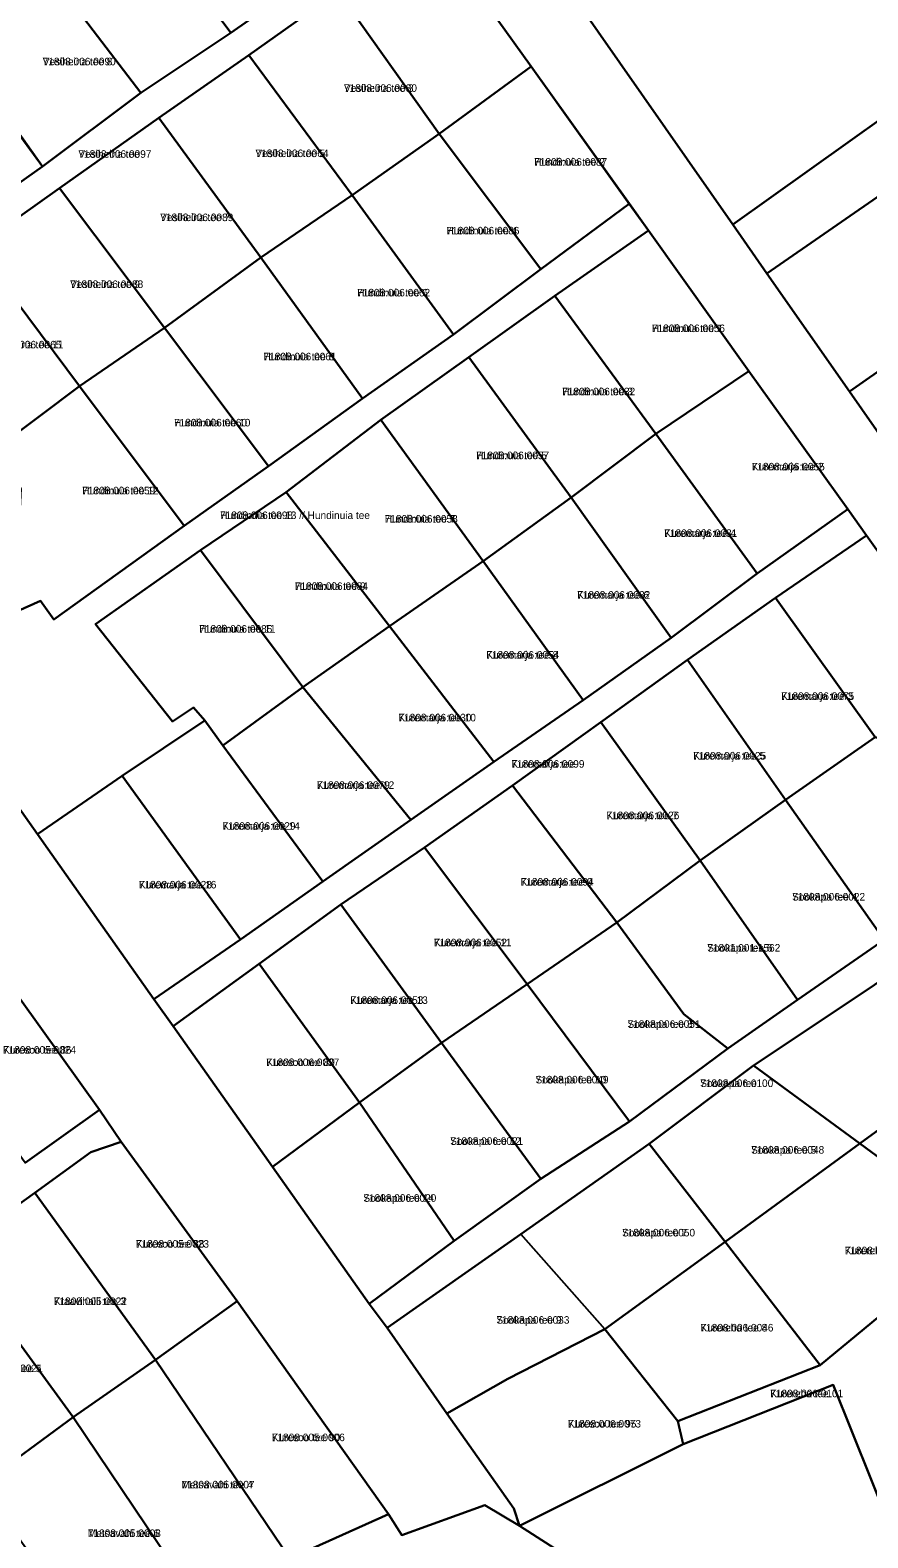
# Model space of a CAD drawing. Extents: x 529768 to 552006, y 6562269 to 6580975.
# Drawn here: x 537073.5 to 537239.9, y 6569374.1 to 6569673.6 of the extents above; entities that cross this region are included whole.
import ezdxf

# ---------------------------------------------------------------- set-up
doc = ezdxf.new("R2010")
doc.units = 0
for name, color, linetype in [('L_AADRESS', 7, 'Continuous'), ('PIIR', 7, 'Continuous'), ('TUNNUS', 7, 'Continuous')]:
    doc.layers.add(name, color=color, linetype=linetype)

msp = doc.modelspace()

# ---------------------------------------------------------------- linework, layer by layer
at = {"layer": 'PIIR'}
for points in [[(537266.4, 6569673.05), (537213.13, 6569635.04), (537177.27, 6569686.31), (537203.34, 6569704.49), (537225.59, 6569720.1), (537248.43, 6569736.1)], [(537261.05, 6569543.39), (537239.66, 6569573.28), (537235.95, 6569578.47), (537216.31, 6569605.91), (537196.34, 6569633.83), (537192.57, 6569639.15), (537173.03, 6569666.4), (537152.81, 6569694.66)], [(537177.27, 6569686.31), (537213.13, 6569635.04), (537219.84, 6569625.32), (537236.26, 6569601.86), (537251.93, 6569579.48)], [(537245.2, 6569642.81), (537219.84, 6569625.32), (537213.13, 6569635.04), (537266.4, 6569673.05)], [(537071.01, 6569558.23), (537075.59, 6569560.29), (537078.22, 6569556.56), (537104.13, 6569575.18), (537120.88, 6569587.03), (537139.57, 6569600.46), (537157.6, 6569613.15), (537174.96, 6569626.16), (537192.55, 6569639.13), (537196.34, 6569633.83), (537177.78, 6569620.87), (537160.65, 6569608.69), (537143.21, 6569596.23), (537124.4, 6569581.87), (537107.37, 6569570.33), (537086.55, 6569555.63), (537101.84, 6569536.3), (537105.98, 6569539.09), (537108.23, 6569536.47), (537091.83, 6569525.51), (537074.98, 6569513.91), (537038.34, 6569565.76)], [(536660.44, 6569597.72), (536680.38, 6569359.64), (536681.71, 6569343.63), (536686.07, 6569338.44), (536784.68, 6569221.92), (536962.4, 6569293.88), (536967.09, 6569295.8), (536965.47, 6569313.36), (536978.54, 6569310.73), (536993.55, 6569314.63), (536997.71, 6569316.46), (537012.75, 6569322.66), (537032.22, 6569330.68), (537054.2, 6569339.74), (537061.66, 6569342.81), (537086.06, 6569353.34), (537106.33, 6569362.09), (537125.11, 6569370.01), (537144.7, 6569378.86), (537147.4, 6569374.65), (537163.87, 6569380.63), (537170.73, 6569376.5), (537249.6, 6569325.97)], [(537038.34, 6569565.76), (537074.98, 6569513.91), (537098.12, 6569481.17), (537101.92, 6569475.79), (537121.67, 6569447.83), (537140.89, 6569420.64), (537144.46, 6569415.89), (537156.29, 6569398.85), (537169.61, 6569380), (537170.73, 6569376.5), (537163.87, 6569380.63), (537147.4, 6569374.65), (537144.7, 6569378.86), (537114.67, 6569421.13), (537091.6, 6569452.84), (537087.31, 6569459.19), (537063.91, 6569491.83)], [(537072.57, 6569448.65), (537087.31, 6569459.19), (537091.6, 6569452.84), (537085.62, 6569450.74), (537074.45, 6569442.68), (537058.12, 6569430.98)], [(537251.88, 6569357.54), (537233.07, 6569404.52), (537203.24, 6569392.77), (537202.16, 6569397.33), (537230.45, 6569408.44), (537262.38, 6569434.81)]]:
    msp.add_lwpolyline(points, dxfattribs=at)
for points in [[(537131.6, 6569685.88), (537113.43, 6569673.07), (537093.32, 6569700.01), (537111.74, 6569713.13)], [(537093.32, 6569700.01), (537113.43, 6569673.07), (537095.55, 6569661.17), (537075.56, 6569687.37)], [(537149.74, 6569698.95), (537152.81, 6569694.66), (537134.74, 6569681.28), (537116.99, 6569668.66), (537099.09, 6569656.2), (537079.39, 6569642.24), (537062.78, 6569630.47), (537047.13, 6569619.41), (537031.67, 6569608.68), (537015.83, 6569597.61), (537012.9, 6569601.76), (537028.62, 6569613.04), (537044.19, 6569623.89), (537059.55, 6569634.95), (537076.02, 6569646.54), (537095.55, 6569661.17), (537113.43, 6569673.07), (537131.6, 6569685.88)], [(537173.03, 6569666.4), (537154.76, 6569653.04), (537134.74, 6569681.28), (537152.81, 6569694.66)], [(537075.56, 6569687.37), (537095.55, 6569661.17), (537076.02, 6569646.54), (537056.52, 6569673.94)], [(537154.76, 6569653.04), (537137.51, 6569640.87), (537116.99, 6569668.66), (537134.74, 6569681.28)], [(537076.02, 6569646.54), (537059.55, 6569634.95), (537039.53, 6569661.72), (537056.18, 6569673.57)], [(537137.51, 6569640.87), (537119.38, 6569628.48), (537099.09, 6569656.2), (537116.99, 6569668.66)], [(537154.76, 6569653.04), (537173.03, 6569666.4), (537192.55, 6569639.13), (537174.96, 6569626.16)], [(537099.09, 6569656.2), (537119.38, 6569628.48), (537100.23, 6569614.48), (537079.39, 6569642.24)], [(537137.51, 6569640.87), (537154.76, 6569653.04), (537174.96, 6569626.16), (537157.6, 6569613.15)], [(537079.39, 6569642.24), (537100.23, 6569614.48), (537083.35, 6569602.94), (537062.78, 6569630.47)], [(537137.51, 6569640.87), (537157.6, 6569613.15), (537139.57, 6569600.46), (537119.38, 6569628.48)], [(537245.2, 6569642.81), (537261.35, 6569619.4), (537236.26, 6569601.86), (537219.84, 6569625.32)], [(537216.31, 6569605.91), (537197.79, 6569593.45), (537177.78, 6569620.87), (537196.34, 6569633.83)], [(537047.13, 6569619.41), (537062.78, 6569630.47), (537083.35, 6569602.94), (537067.23, 6569590.84)], [(537139.57, 6569600.46), (537120.88, 6569587.03), (537100.23, 6569614.48), (537119.38, 6569628.48)], [(537160.65, 6569608.69), (537177.78, 6569620.87), (537197.79, 6569593.45), (537181.03, 6569580.83)], [(537236.26, 6569601.86), (537261.35, 6569619.4), (537276.9, 6569597.32), (537251.93, 6569579.48)], [(537100.23, 6569614.48), (537120.88, 6569587.03), (537104.13, 6569575.18), (537083.35, 6569602.94)], [(537181.03, 6569580.83), (537163.54, 6569568.18), (537143.21, 6569596.23), (537160.65, 6569608.69)], [(537235.95, 6569578.47), (537217.96, 6569565.73), (537197.79, 6569593.45), (537216.31, 6569605.91)], [(537068.21, 6569572.85), (537071.43, 6569575.92), (537071.74, 6569582.52), (537067.23, 6569590.84), (537083.35, 6569602.94), (537104.13, 6569575.18), (537078.22, 6569556.56), (537075.59, 6569560.29), (537071.01, 6569558.23), (537063.64, 6569571.75)], [(537124.4, 6569581.87), (537143.21, 6569596.23), (537163.54, 6569568.18), (537144.89, 6569555.25)], [(537197.79, 6569593.45), (537217.96, 6569565.73), (537200.85, 6569552.93), (537181.03, 6569580.83)], [(537124.4, 6569581.87), (537144.89, 6569555.25), (537127.73, 6569543.11), (537107.37, 6569570.33)], [(537181.03, 6569580.83), (537200.85, 6569552.93), (537183.41, 6569540.51), (537163.54, 6569568.18)], [(537235.95, 6569578.47), (537239.66, 6569573.28), (537221.56, 6569560.9), (537204.1, 6569548.53), (537186.91, 6569536.16), (537169.38, 6569523.6), (537151.84, 6569511.28), (537135.22, 6569499.93), (537119.01, 6569488.15), (537101.92, 6569475.79), (537098.12, 6569481.17), (537115.33, 6569492.97), (537131.66, 6569504.51), (537149.13, 6569516.74), (537165.65, 6569528.3), (537183.41, 6569540.51), (537200.85, 6569552.93), (537217.96, 6569565.73)], [(537239.66, 6569573.28), (537261.05, 6569543.39), (537263.43, 6569526.68), (537241.37, 6569533.21), (537221.56, 6569560.9)], [(537107.37, 6569570.33), (537127.73, 6569543.11), (537111.83, 6569531.55), (537108.23, 6569536.47), (537105.98, 6569539.09), (537101.84, 6569536.3), (537086.55, 6569555.63)], [(537183.41, 6569540.51), (537165.65, 6569528.3), (537144.89, 6569555.25), (537163.54, 6569568.18)], [(537241.37, 6569533.21), (537223.58, 6569520.73), (537204.1, 6569548.53), (537221.56, 6569560.9)], [(537144.89, 6569555.25), (537165.65, 6569528.3), (537149.13, 6569516.74), (537127.73, 6569543.11)], [(537204.1, 6569548.53), (537223.58, 6569520.73), (537206.6, 6569508.71), (537186.91, 6569536.16)], [(537149.13, 6569516.74), (537131.66, 6569504.51), (537111.83, 6569531.55), (537127.73, 6569543.11)], [(537091.83, 6569525.51), (537108.23, 6569536.47), (537111.83, 6569531.55), (537131.66, 6569504.51), (537115.33, 6569492.97)], [(537186.91, 6569536.16), (537206.6, 6569508.71), (537190.09, 6569496.38), (537169.38, 6569523.6)], [(537241.37, 6569533.21), (537263.43, 6569526.68), (537265.6, 6569511.5), (537261.64, 6569506.58), (537243.17, 6569492.95), (537223.58, 6569520.73)], [(537074.98, 6569513.91), (537091.83, 6569525.51), (537115.33, 6569492.97), (537098.12, 6569481.17)], [(537169.38, 6569523.6), (537190.09, 6569496.38), (537172.27, 6569484.15), (537151.84, 6569511.28)], [(537223.58, 6569520.73), (537243.17, 6569492.95), (537225.98, 6569481.04), (537206.6, 6569508.71)], [(537151.84, 6569511.28), (537172.27, 6569484.15), (537155.27, 6569472.46), (537135.22, 6569499.93)], [(537265.6, 6569511.5), (537266.97, 6569501.86), (537246.86, 6569487.92), (537240.36, 6569483.41), (537217.2, 6569467.96), (537196.48, 6569452.42), (537171.01, 6569434.5), (537144.46, 6569415.89), (537140.89, 6569420.64), (537157.77, 6569433.15), (537174.98, 6569445.45), (537192.58, 6569456.86), (537212.1, 6569471.37), (537225.98, 6569481.04), (537243.17, 6569492.95), (537261.64, 6569506.58)], [(537190.09, 6569496.38), (537206.6, 6569508.71), (537225.98, 6569481.04), (537212.1, 6569471.37), (537203.36, 6569478.2)], [(537135.22, 6569499.93), (537155.27, 6569472.46), (537138.98, 6569460.59), (537119.01, 6569488.15)], [(537190.09, 6569496.38), (537203.36, 6569478.2), (537212.1, 6569471.37), (537192.58, 6569456.86), (537172.27, 6569484.15)], [(537048.99, 6569480.8), (537063.91, 6569491.83), (537087.31, 6569459.19), (537072.57, 6569448.65), (537060.58, 6569465.12)], [(537119.01, 6569488.15), (537138.98, 6569460.59), (537121.67, 6569447.83), (537101.92, 6569475.79)], [(537238.31, 6569452.5), (537217.2, 6569467.96), (537240.36, 6569483.41), (537246.86, 6569487.92), (537260.69, 6569468.76)], [(537172.27, 6569484.15), (537192.58, 6569456.86), (537174.98, 6569445.45), (537155.27, 6569472.46)], [(537155.27, 6569472.46), (537174.98, 6569445.45), (537157.77, 6569433.15), (537138.98, 6569460.59)], [(537262.63, 6569470.04), (537285.95, 6569456.7), (537262.38, 6569434.81), (537238.31, 6569452.5), (537260.69, 6569468.76)], [(537238.31, 6569452.5), (537211.62, 6569432.95), (537196.48, 6569452.42), (537217.2, 6569467.96)], [(537138.98, 6569460.59), (537157.77, 6569433.15), (537140.89, 6569420.64), (537121.67, 6569447.83)], [(537085.62, 6569450.74), (537091.6, 6569452.84), (537114.67, 6569421.13), (537098.41, 6569409.48), (537074.45, 6569442.68)], [(537171.01, 6569434.5), (537196.48, 6569452.42), (537211.62, 6569432.95), (537187.68, 6569415.62)], [(537262.38, 6569434.81), (537230.45, 6569408.44), (537211.62, 6569432.95), (537238.31, 6569452.5)], [(537074.45, 6569442.68), (537098.41, 6569409.48), (537082.1, 6569398.14), (537058.12, 6569430.98)], [(537187.68, 6569415.62), (537168.4, 6569405.75), (537156.29, 6569398.85), (537144.46, 6569415.89), (537171.01, 6569434.5)], [(537058.12, 6569430.98), (537082.1, 6569398.14), (537063.67, 6569384.61), (537040.96, 6569418.86)], [(537211.62, 6569432.95), (537230.45, 6569408.44), (537202.16, 6569397.33), (537187.68, 6569415.62)], [(537114.67, 6569421.13), (537144.7, 6569378.86), (537125.11, 6569370.01), (537098.41, 6569409.48)], [(537169.61, 6569380), (537156.29, 6569398.85), (537168.4, 6569405.75), (537187.68, 6569415.62), (537202.16, 6569397.33), (537203.24, 6569392.77), (537170.73, 6569376.5)], [(537098.41, 6569409.48), (537125.11, 6569370.01), (537106.33, 6569362.09), (537082.1, 6569398.14)], [(537251.88, 6569357.54), (537249.6, 6569325.97), (537170.73, 6569376.5), (537203.24, 6569392.77), (537233.07, 6569404.52)], [(537082.1, 6569398.14), (537106.33, 6569362.09), (537086.06, 6569353.34), (537063.67, 6569384.61)]]:
    msp.add_lwpolyline(points, close=True, dxfattribs=at)

# ---------------------------------------------------------------- texts
at = {"layer": 'L_AADRESS'}
for s, p in [('Vesiheina tee 8', (537076.04, 6569666.65)), ('Vesiheina tee 3', (537135.88, 6569661.38)), ('Vesiheina tee', (537083.13, 6569648.28)), ('Vesiheina tee 5', (537118.3, 6569648.42)), ('Hundinuia tee 2', (537173.65, 6569646.71)), ('Vesiheina tee 7', (537099.39, 6569635.7)), ('Hundinuia tee 4', (537156.23, 6569633.06)), ('Vesiheina tee 9', (537081.5, 6569622.42)), ('Hundinuia tee 6', (537138.49, 6569620.74)), ('Hundinuia tee 1', (537197.05, 6569613.66)), ('Vesiheina tee 11', (537065.24, 6569610.42)), ('Hundinuia tee 8', (537119.9, 6569608.05)), ('Hundinuia tee 3', (537179.22, 6569601.1)), ('Hundinuia tee 10', (537102.12, 6569594.92)), ('Hundinuia tee 5', (537162.12, 6569588.41)), ('Kuremarja tee 2', (537216.87, 6569586.18)), ('Hundinuia tee 12', (537083.89, 6569581.43)), ('Hundinuia tee 13 // Hundinuia tee', (537111.26, 6569576.52)), ('Hundinuia tee 7', (537143.97, 6569575.81)), ('Kuremarja tee 4', (537199.5, 6569572.97)), ('Hundinuia tee 9', (537126.13, 6569562.44)), ('Kuremarja tee 6', (537182.2, 6569560.7)), ('Hundinuia tee 11', (537107.14, 6569553.95)), ('Kuremarja tee 8', (537164.15, 6569548.79)), ('Kuremarja tee 3', (537222.73, 6569540.6)), ('Kuremarja tee 10', (537146.69, 6569536.33)), ('Kuremarja tee 5', (537205.24, 6569528.75)), ('Kuremarja tee', (537169.14, 6569527.13)), ('Kuremarja tee 12', (537130.48, 6569522.92)), ('Kuremarja tee 7', (537187.99, 6569516.9)), ('Kuremarja tee 14', (537111.74, 6569514.8)), ('Kuremarja tee 9', (537170.97, 6569503.7)), ('Kuremarja tee 16', (537095.15, 6569503.14)), ('Sookäpa tee 4', (537224.89, 6569500.74)), ('Kuremarja tee 11', (537153.75, 6569491.65)), ('Sookäpa tee 6', (537208.04, 6569490.6)), ('Kuremarja tee 13', (537137.14, 6569480.21)), ('Sookäpa tee 8', (537192.19, 6569475.45)), ('Kuresoo tee 86', (537068.15, 6569470.32)), ('Kuresoo tee 89', (537120.45, 6569467.86)), ('Sookäpa tee 10', (537173.93, 6569464.41)), ('Sookäpa tee', (537206.64, 6569463.7)), ('Sookäpa tee 12', (537156.98, 6569452.21)), ('Sookäpa tee 5', (537216.76, 6569450.46)), ('Sookäpa tee 14', (537139.72, 6569440.9)), ('Sookäpa tee 7', (537191.11, 6569434.02)), ('Kuresoo tee 88', (537094.56, 6569431.79)), ('Kurereha tee 6', (537235.33, 6569430.47)), ('Kraavihalli tee 3', (537078.26, 6569420.39)), ('Sookäpa tee 9', (537166.16, 6569416.68)), ('Kurereha tee 8', (537206.68, 6569415.14)), ('Kraavihalli tee 5', (537061.53, 6569407.07)), ('Kurereha tee', (537220.54, 6569402.07)), ('Kuresoo tee 95', (537180.36, 6569396.06)), ('Kuresoo tee 90', (537121.55, 6569393.35)), ('Metsavahi tee 4', (537103.61, 6569383.97)), ('Metsavahi tee 6', (537085, 6569374.32))]:
    msp.add_text(s, height=1.5, dxfattribs=at).set_placement(p)
at = {"layer": 'TUNNUS'}
for s, p in [('71808:006:0090', (537076.04, 6569666.65)), ('71808:006:0080', (537135.88, 6569661.38)), ('71808:006:0097', (537083.13, 6569648.28)), ('71808:006:0064', (537118.3, 6569648.42)), ('71808:006:0087', (537173.65, 6569646.71)), ('71808:006:0089', (537099.39, 6569635.7)), ('71808:006:0086', (537156.23, 6569633.06)), ('71808:006:0088', (537081.5, 6569622.42)), ('71808:006:0062', (537138.49, 6569620.74)), ('71808:006:0056', (537197.05, 6569613.66)), ('71808:006:0065', (537065.24, 6569610.42)), ('71808:006:0061', (537119.9, 6569608.05)), ('71808:006:0032', (537179.22, 6569601.1)), ('71808:006:0060', (537102.12, 6569594.92)), ('71808:006:0057', (537162.12, 6569588.41)), ('71808:006:0055', (537216.87, 6569586.18)), ('71808:006:0059', (537083.89, 6569581.43)), ('71808:006:0098', (537111.26, 6569576.52)), ('71808:006:0058', (537143.97, 6569575.81)), ('71808:006:0031', (537199.5, 6569572.97)), ('71808:006:0084', (537126.13, 6569562.44)), ('71808:006:0082', (537182.2, 6569560.7)), ('71808:006:0085', (537107.14, 6569553.95)), ('71808:006:0054', (537164.15, 6569548.79)), ('71808:006:0075', (537222.73, 6569540.6)), ('71808:006:0030', (537146.69, 6569536.33)), ('71808:006:0025', (537205.24, 6569528.75)), ('71808:006:0099', (537169.14, 6569527.13)), ('71808:006:0079', (537130.48, 6569522.92)), ('71808:006:0026', (537187.99, 6569516.9)), ('71808:006:0029', (537111.74, 6569514.8)), ('71808:006:0028', (537095.15, 6569503.14)), ('71808:006:0094', (537170.97, 6569503.7)), ('71808:006:0022', (537224.89, 6569500.74)), ('71808:006:0052', (537153.75, 6569491.65)), ('71801:001:1562', (537208.04, 6569490.6)), ('71808:006:0053', (537137.14, 6569480.21)), ('71808:006:0051', (537192.19, 6569475.45)), ('71808:005:0024', (537068.15, 6569470.32)), ('71808:006:0027', (537120.45, 6569467.86)), ('71808:006:0049', (537173.93, 6569464.41)), ('71808:006:0100', (537206.64, 6569463.7)), ('71808:006:0021', (537156.98, 6569452.21)), ('71808:006:0048', (537216.76, 6569450.46)), ('71808:006:0020', (537139.72, 6569440.9)), ('71808:006:0050', (537191.11, 6569434.02)), ('71808:005:0023', (537094.56, 6569431.79)), ('71808:006:0047', (537235.33, 6569430.47)), ('71808:005:0022', (537078.26, 6569420.39)), ('71808:006:0033', (537166.16, 6569416.68)), ('71808:006:0046', (537206.68, 6569415.14)), ('71808:005:0021', (537061.53, 6569407.07)), ('71808:006:0101', (537220.54, 6569402.07)), ('71808:006:0073', (537180.36, 6569396.06)), ('71808:005:0006', (537121.55, 6569393.35)), ('71808:005:0007', (537103.61, 6569383.97)), ('71808:005:0008', (537085, 6569374.32))]:
    msp.add_text(s, height=1.5, dxfattribs=at).set_placement(p)

doc.saveas('drawing.dxf')
